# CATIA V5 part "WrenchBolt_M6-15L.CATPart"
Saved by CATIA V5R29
Part number: WrenchBolt_M6-15L
Bounding box of the stored display mesh (mm): x -5.11 to 5.11, y -5.11 to 5.11, z -15 to 6
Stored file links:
  C:\Users\CDL\Desktop\PostConveyor\PostConveyor_Bolt ETC\WrenchBolt_M6-15L.CATPart
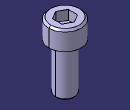
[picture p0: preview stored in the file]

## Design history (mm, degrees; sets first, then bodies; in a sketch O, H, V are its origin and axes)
Body1 (main body)
  Sketch1 on xy-plane, origin (0, 0, 0), H (1, 0, 0), V (0, 1, 0)
    circle A1 centre (0, 0) radius 5.11
    radius A1 = 5.11
  Pad1: profile Sketch1, direction (0, 0, 1), length 6
  Sketch2 on start face of Pad1, origin (0, 0, 0), H (1, 0, 0), V (0, -1, 0)
    circle A1 centre (0, 0) radius 3
    radius A1 = 3
  Pad2: profile Sketch2, direction (0, 0, -1), length 15
  Sketch3 on end face of Pad1, origin (0, 0, 6), H (1, 0, 0), V (0, 1, 0)
    point P1 (2.5475, 0)
    construction circle A1 centre (0, 0) radius 2.9416
    construction circle A2 centre (0, 0) radius 2.5475
    point P2 (2.5475, -1.4708)
    point P3 (2.5475, 1.4708)
    point P4 (0, 2.9416)
    point P5 (-2.5475, 1.4708)
    point P6 (-2.5475, -1.4708)
    point P7 (0, -2.9416)
    line L1 (2.5475, -1.4708) -> (2.5475, 1.4708)
    line L2 (2.5475, 1.4708) -> (0, 2.9416)
    line L3 (0, 2.9416) -> (-2.5475, 1.4708)
    line L4 (-2.5475, 1.4708) -> (-2.5475, -1.4708)
    line L5 (-2.5475, -1.4708) -> (0, -2.9416)
    line L6 (0, -2.9416) -> (2.5475, -1.4708)
    construction line L7 (0, 0) -> (2.5475, 0)
    radius A2 = 2.5475
    coincidence: A1 P2, A1 P3, A1 P4, A1 P5, A1 P6, A1 P7
    tangency: A2 L1, A2 L2, A2 L3, A2 L4, A2 L5, A2 L6
    midpoint: P1 L1
    horizontal: L7 H
  Pocket1: profile Sketch3, direction (0, 0, -1), length 3
  Thread1: "M6", diameter 6, depth 15, pitch 1, on face of Pad2 from Sketch2.A1, from end face of Pad2
  Chamfer1: length 0.6, angle 45, on end face of Pad2; edge [face of Pad1 from Sketch1.A1 | end face of Pad1]
  Fillet1: radius 0.25, on edge [start face of Pad1 | face of Pad2 from Sketch2.A1]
